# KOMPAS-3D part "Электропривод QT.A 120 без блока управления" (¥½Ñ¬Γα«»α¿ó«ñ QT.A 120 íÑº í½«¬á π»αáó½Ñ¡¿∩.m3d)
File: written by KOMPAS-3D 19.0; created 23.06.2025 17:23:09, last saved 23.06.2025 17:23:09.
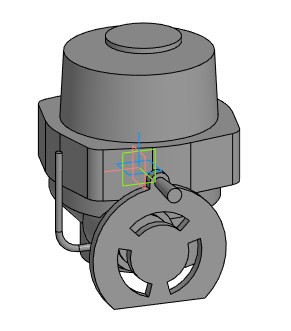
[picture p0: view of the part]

Document properties: Автор: Евгений; Полное имя файла: E:\Dendor Работа Сачек\3D для проектировщиков\3.5 Тип QT.А Электропривод\stp_Электропривод QT.A без блока управления\Электропривод QT.A 120 без блока управления.m3d

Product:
- Part/product: Электропривод QT.A 120 без блока управления

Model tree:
1. Операция без истории:1  (labels: Электропривод QT.A 120 без блока управления)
